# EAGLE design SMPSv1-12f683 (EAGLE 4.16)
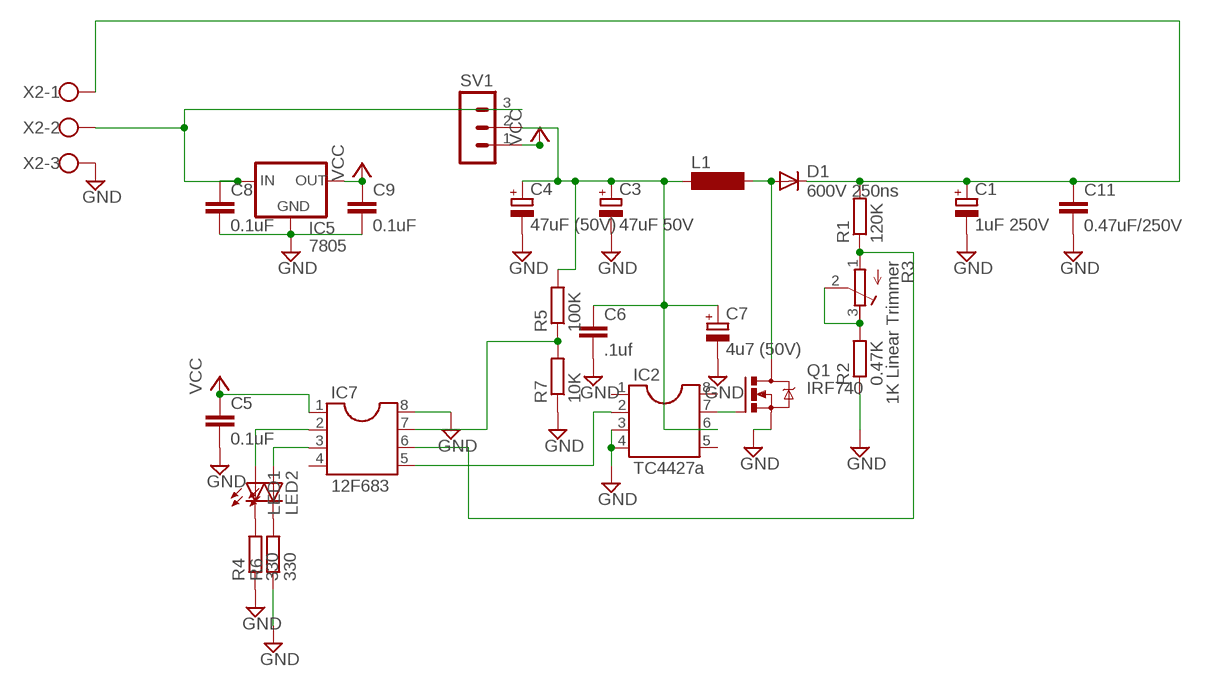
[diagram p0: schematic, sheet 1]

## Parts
C1  1uF 250V  CPOL-EUE2.5-6  [E2,5-6]
C3  47uF 50V  CPOL-EUE2.5-7  [E2,5-7]
C4  47uF (50V)  CPOL-EUE2.5-7  [E2,5-7]
C5  0.1uF  C2.5/2  [C2.5-2]
C6  .1uf  C2.5/2  [C2.5-2]
C7  4u7 (50V)  CPOL-EUE2.5-5  [E2,5-5]
C8  0.1uF  C2.5/2  [C2.5-2]
C9  0.1uF  C2.5/2  [C2.5-2]
C11  0.47uF/250V  C22/6  [C20.5B4]
D1  600V 250ns  BY448  [SOD57-10]
IC2  TC4427a  DIL8S  [SOCKED-08]
IC5  7805  78XXS  [78XXS]
IC7  12F683  DIL8S  [SOCKED-08]
L1  BS11  [BS11]
LED1  LED5MM  [LED5MM]
LED2  LED5MM  [LED5MM]
Q1  IRF740  [TO220BV]
R1  120K  R-EU_0204/7  [0204/7]
R2  0.47K  R-EU_0204/7  [0204/7]
R3  1K Linear Trimmer  R-TRIMM3339P  [RTRIM3339P]
R4  330  R-EU_0204/7  [0204/7]
R5  100K  R-EU_0204/7  [0204/7]
R6  330  R-EU_0204/7  [0204/7]
R7  10K  R-EU_0204/2V  [0204V]
SV1  MA03-1  [MA03-1]
X2  W237-3E  [W237-3E]

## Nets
GND: C1.- C3.- C4.- C5.2 C6.2 C7.- C8.2 C9.2 C11.2 IC2.3 IC2.4 IC5.GND IC7.8 Q1.S R2.1 R4.1 R6.1 R7.1 X2.3
N$1: D1.A L1.2 Q1.D
N$2: C3.+ C4.+ C6.1 C7.+ IC2.6 L1.1 R5.2 SV1.2
N$4: IC7.6 R1.1 R3.1(E)
N$5: R2.2 R3.2(S) R3.3(A)
N$6: IC2.7 Q1.G
N$7: IC2.2 IC7.5
N$8: LED1.K(C) R4.2
N$9: LED2.K(C) R6.2
N$10: C1.+ C11.1 D1.C R1.2 X2.1
N$13: IC7.3 LED2.A
N$14: IC7.2 LED1.A
N$17: C8.1 IC5.IN SV1.3 X2.2
N$30: IC7.7 R5.1 R7.2
VCC: C5.1 C9.1 IC5.OUT IC7.1 SV1.1
Unconnected: IC2.1 IC2.5 IC2.8 IC7.4

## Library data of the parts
C1 C3 C4 C7 = rcl:CPOL-EU: POLARIZED CAPACITOR, European symbol
C5 C6 C8 C9 = capacitor-wima:C: CAPACITOR
C11 = capacitor-HV:C: CAPACITOR
D1 = diode:BY448: DIODE
IC2 IC7 = ic-package:DIL8: Dual In Line
IC5 = v-reg:78XXS: VOLTAGE REGULATOR
L1 = inductor-neosid:BS: INDUCTOR
LED1 LED2 = led:LED: LED
Q1 = transistor-power:IRF740: N-CHANNEL MOS FET
R1 R2 R4-R7 = rcl:R-EU_: RESISTOR, European symbol
R3 = rcl:R-TRIMM: Trimm resistor
SV1 = con-lstb:MA03-1: PIN HEADER
X2 = con-wago-508:W237-3E: WAGO SREW CLAMP

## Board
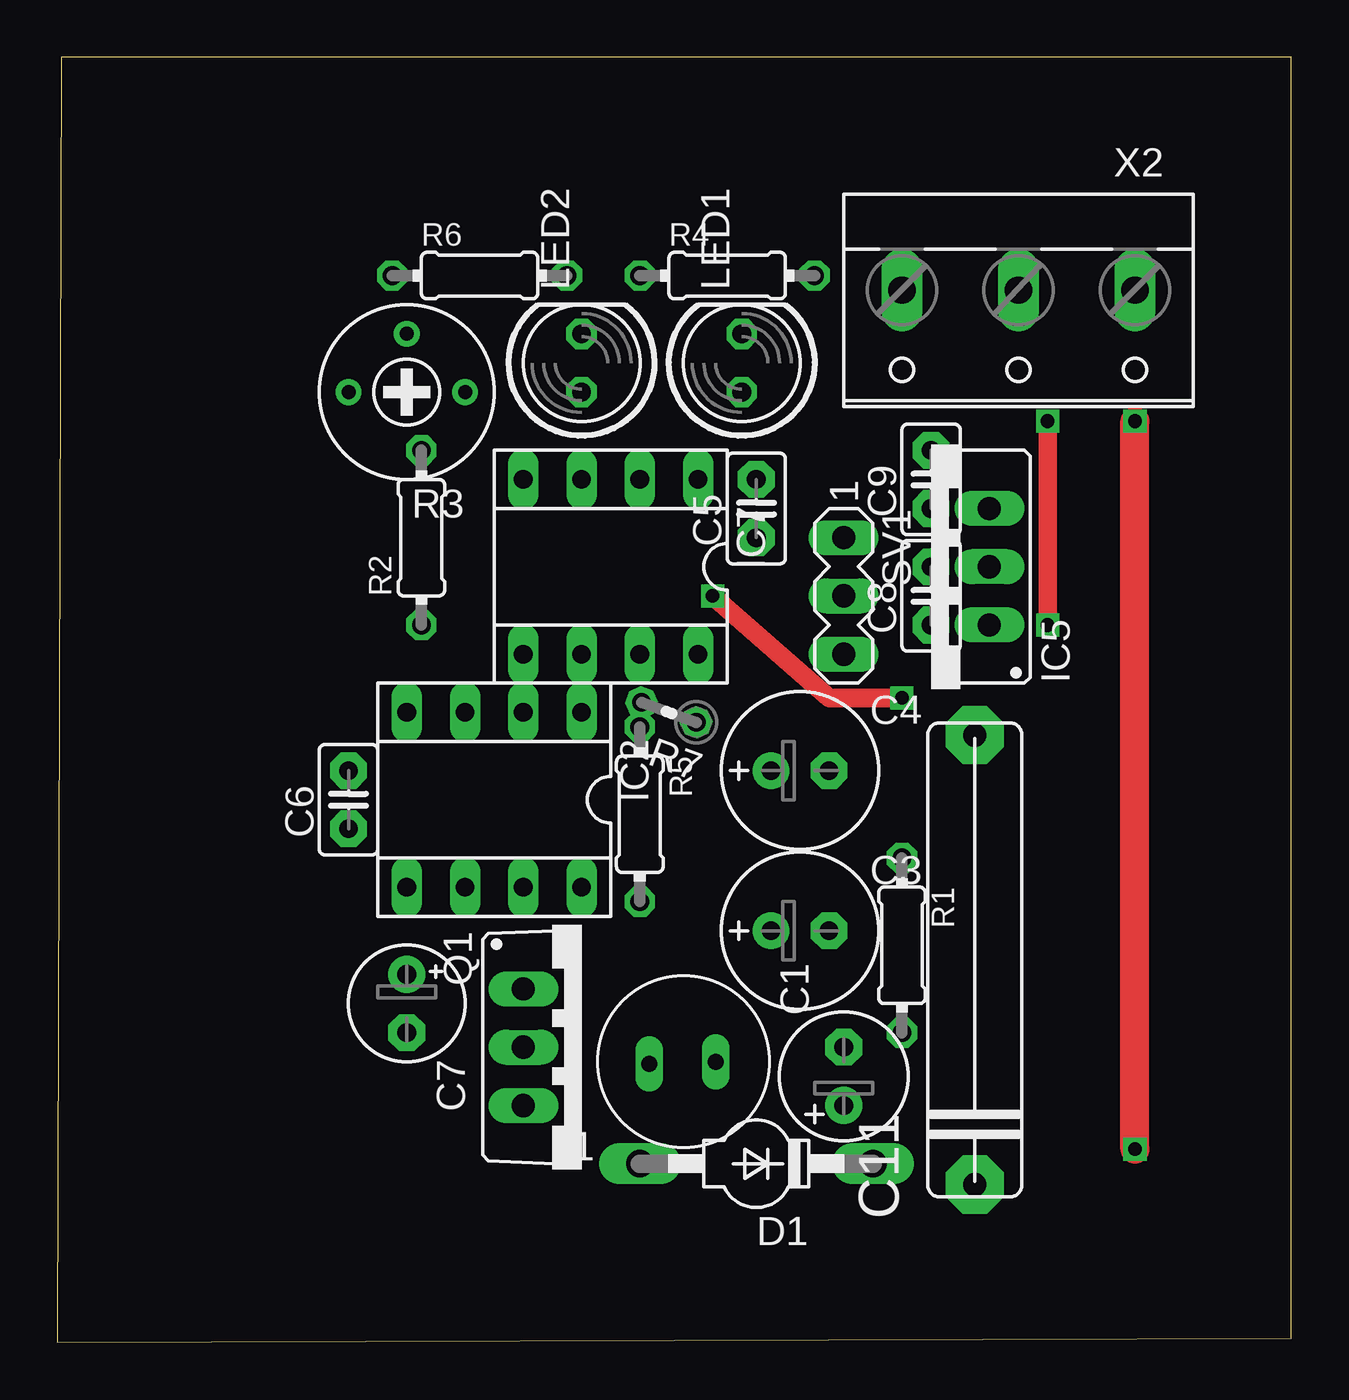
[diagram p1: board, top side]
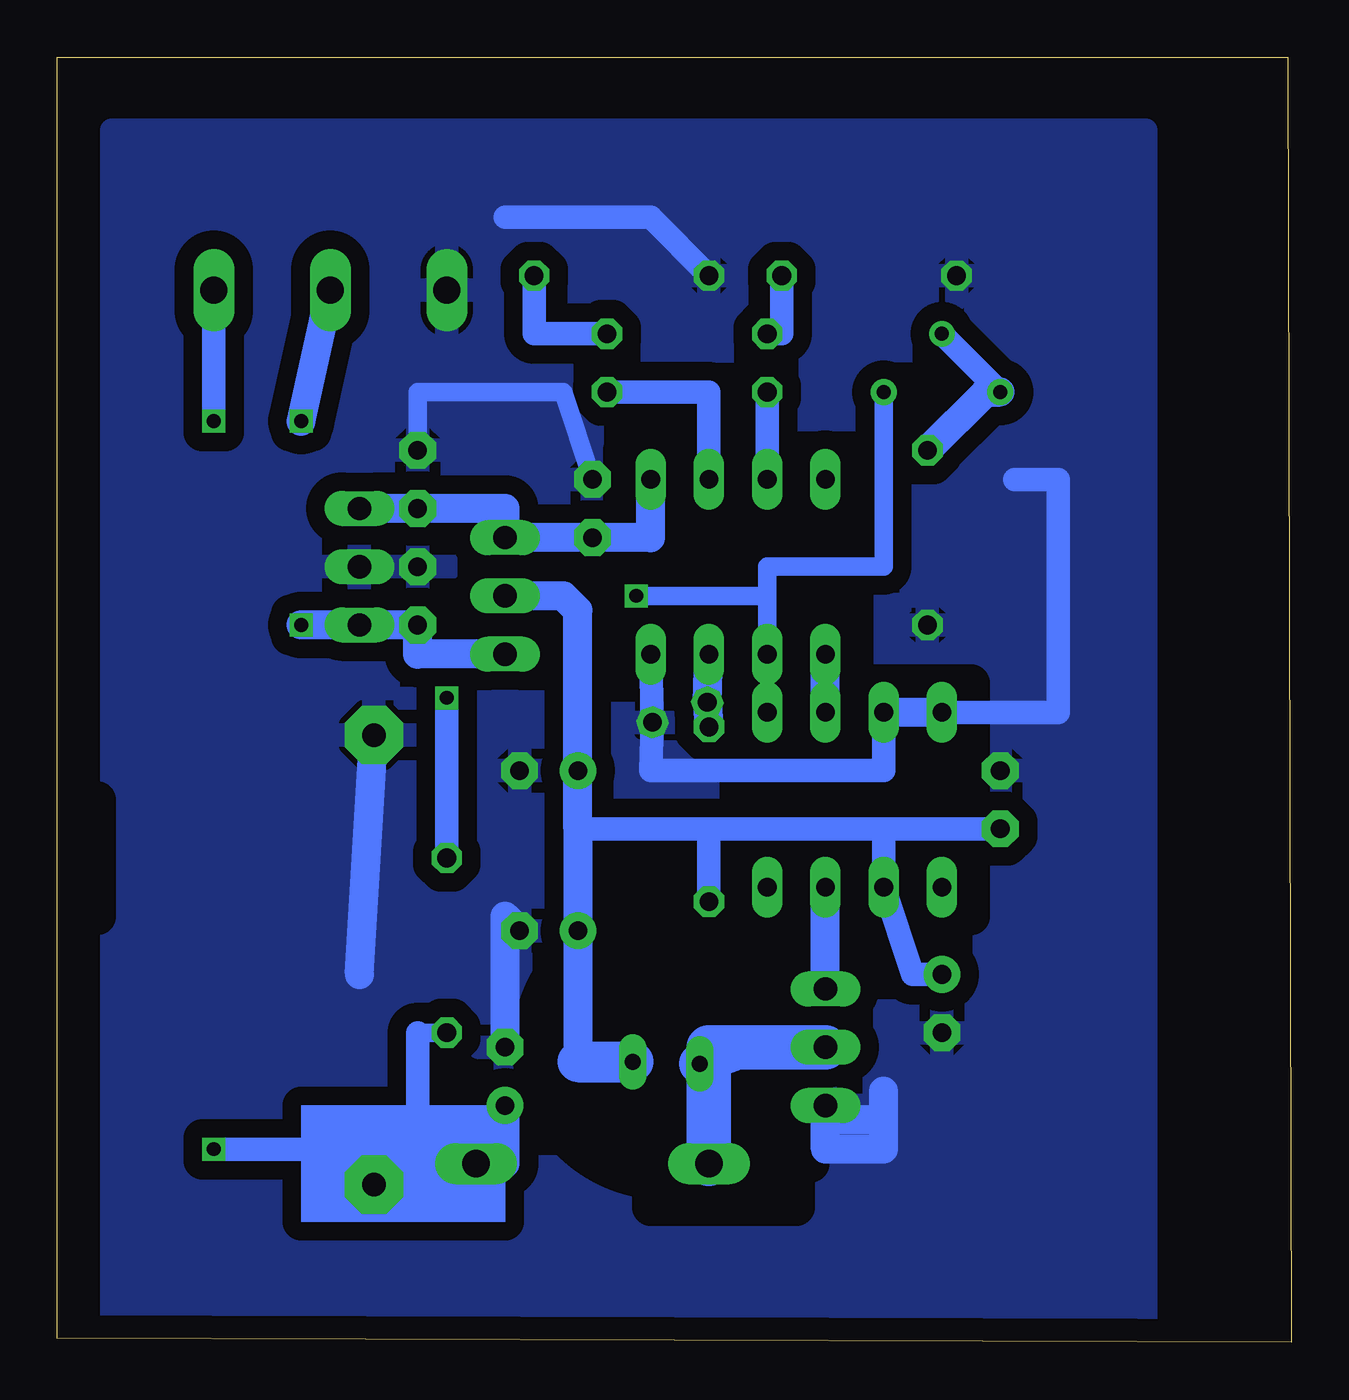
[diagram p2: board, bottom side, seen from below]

Size 53.81 x 56.04 mm. Coordinates in mm from the lower left corner, seen from the top.
Outline: 0,0 53.81,0.17 53.81,56.04 0.16,56.04 0,0
Copper layers (1*16): Top 0.035mm / dielectric 1.5mm / Bottom 0.035mm
Design rules "default": minimum track width 10mil, minimum drill 24mil, track to track 8mil, track to pad 8mil, pad to pad 8mil, via to via 8mil, smd to smd 8mil, copper to edge 40mil, drill to drill 8mil, minimum pad ring 10mil, minimum via ring 8mil, stop-mask expansion 4mil, vias tented up to drill 0mil, thermal gap 10mil
bRestrict: area 14,18.6 to 24.1,28.7; area 22.7,8.3 to 31.9,17.4; area 19,28.7 to 29.2,38.9; area 71.1,5.9 to 72.4,11; area 20.9,7.8 to 22.2,10.3; area 54.6,32.5 to 74.9,37.6; area 52.1,18.6 to 69.8,23.7; area 21.6,5.9 to 27.9,8.4

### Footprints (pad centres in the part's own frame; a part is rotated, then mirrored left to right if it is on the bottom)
E2,5-6 = drill 0.813 pad 1.6 round: + -1.27,0 | drill 0.813 pad 1.6 octagon: - 1.27,0
E2,5-7 = drill 0.813 pad 1.6 round: + -1.27,0 | drill 0.813 pad 1.6 octagon: - 1.27,0
C2.5-2 = drill 0.813 pad 1.6 octagon: 1 -1.27,0; 2 1.27,0
E2,5-5 = drill 0.813 pad 1.6 round: + -1.27,0 | drill 0.813 pad 1.6 octagon: - 1.27,0
C20.5B4 = drill 1.016 pad 2.54 octagon: 1 -9.803,0; 2 9.803,0
SOD57-10 = drill 1.194 long: A 5.08,0; C -5.08,0
SOCKED-08 = drill 0.813 long: 1 -3.81,-3.81; 2 -1.27,-3.81; 3 1.27,-3.81; 4 3.81,-3.81; 5 3.81,3.81; 6 1.27,3.81; 7 -1.27,3.81; 8 -3.81,3.81
78XXS = drill 1.016 long: GND 0,-2.54; IN -2.54,-2.54; OUT 2.54,-2.54
BS11 = drill 0.7 long: 1 -1.415,0; 2 1.502,0.087
LED5MM = drill 0.813 octagon: A -1.27,0; K 1.27,0
TO220BV = drill 1.016 long: D 0,-2.54; G -2.54,-2.54; S 2.54,-2.54
0204/7 = drill 0.813 octagon: 1 -3.81,0; 2 3.81,0
RTRIM3339P = drill 0.61 round: 1 -2.54,0; 2 0,-2.54; 3 2.54,0
0204V = drill 0.813 octagon: 1 -1.27,0; 2 1.27,0
MA03-1 = drill 1.016 long: 1 -2.54,0; 2 0,0; 3 2.54,0
W237-3E = drill 1.194 long: 1 -5.08,-0.635; 2 0,-0.635; 3 5.08,-0.635

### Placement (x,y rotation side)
C1  34.28,11.6 90 top
C3  32.38,17.95 0 top
C4  32.38,24.93 0 top
C5  30.48,36.36 90 top
C6  12.7,23.66 90 top
C7  15.23,14.77 270 top
C8  38.09,32.55 90 top
C9  38.09,37.63 90 top
C11  40,16.68 90 top
D1  30.48,7.79 180 top
IC2  19.05,23.66 180 top
IC5  38.09,33.82 90 top
IC7  24.12,33.82 180 top
L1  27.3,12.23 180 top
LED1  29.84,42.71 90 top
LED2  22.86,42.71 90 top
Q1  22.86,12.87 270 top
R1  36.83,17.31 270 top
R2  15.87,35.09 90 top
R3  15.23,41.44 180 top
R4  29.21,46.52 0 top
R5  25.39,23.03 270 top
R6  18.41,46.52 0 top
R7  26.66,27.47 160 top
SV1  34.28,32.55 270 top
X2  41.91,45.25 180 top

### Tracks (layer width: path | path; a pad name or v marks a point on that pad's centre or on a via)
GND
  Bottom 0.813: C5.2 31.75,41.44 38.09,41.44 C9.2
  Bottom 1.016: 34.28,49.06 27.93,49.06 R4.1 | 12.06,37.63 10.16,37.63 10.16,27.47 IC2.4 IC2.3 17.77,24.93 27.93,24.93 R7.1 IC7.8
  Bottom 1.27: IC2.4 IC2.3 | 20.32,9.69 Q1.S | 20.32,9.69 20.32,8.42 17.77,8.42 17.77,9.69 | 17.77,9.69 20.32,9.69 | 17.77,9.69 17.77,10.96 | C1.- 34.28,18.58 C3.- | 40.64,16.04 C11.2
  pour Bottom (isolate 0.813): 6.35,52.87 51.43,52.87 51.43,0.8 6.35,0.8
N$1
  Bottom 1.778: L1.2 24.12,12.78 25.39,12.87
  Bottom 1.93: Q1.D 25.39,12.87 D1.A
N$2
  Bottom 1.016: C7.+ 16.51,16.04 IC2.6 17.77,22.39 | 17.77,22.39 C6.1 | 17.77,22.39 25.39,22.39 | 25.39,22.39 31.11,22.39 | 25.39,22.39 R5.2
  Bottom 1.27: 31.11,12.23 C3.+ 31.11,22.39 C4.+ 31.11,31.91 31.75,32.55 SV1.2
  Bottom 1.778: 31.11,12.23 L1.1
N$4  (via drill 0.6)
  Top 0.813: v36.83,28.11 33.65,28.11 v28.57,32.55
  Bottom 0.813: v28.57,32.55 22.86,32.55 IC7.6 22.86,33.82 17.77,33.82 R3.1
  Bottom 1.016: v36.83,28.11 R1.1
N$5
  Bottom 1.016: R3.3 R3.2
  Bottom 1.27: R3.3 13.33,41.44 R2.2
N$6
  Bottom 1.27: Q1.G IC2.7
N$7
  Bottom 1.27: IC2.2 IC7.5
N$8
  Bottom 1.016: LED1.K 33.02,43.98 R4.2
N$9
  Bottom 1.016: LED2.K 22.22,43.98 R6.2
N$10  (via drill 0.6)
  Top 1.27: v46.98,8.42 v46.98,40.17
  Bottom 0.813: 38.09,13.5 R1.2 | 38.09,8.42 38.4,8.11 38.41,8.11
  Bottom 1.016: 36.83,7.15 36.83,7.35 36.86,7.35 | 38.09,13.5 38.09,8.42 v46.98,8.42 | v46.98,40.17 X2.1
  Bottom 1.27: 38.09,7.79 38.41,8.11 39.34,9.08 41.25,6.6 | 38.09,7.79 38.09,5.88 | 38.09,7.79 C11.1 | C1.+ 34.28,7.79 D1.C
  Bottom 1.93: D1.C 36.86,7.35 41.25,6.6
N$13
  Bottom 1.016: IC7.3 LED2.A
N$14
  Bottom 1.016: LED1.A 25.39,41.44 IC7.2
N$17  (via drill 0.6)
  Top 0.813: v43.17,31.28 v43.17,40.17
  Bottom 1.27: v43.17,31.28 IC5.IN C8.1 38.09,30.01 SV1.3 | v43.17,40.17 X2.2
N$30
  Bottom 0.813: R7.2 25.39,27.9
  Bottom 1.27: R5.1 R7.2 IC7.7
VCC
  Bottom 1.016: C5.1 30.48,35.12
  Bottom 1.27: IC5.OUT C9.1 34.28,36.36 SV1.1 C5.1 27.93,35.09 IC7.1
(copper drawn outside any net)
  shapes: Bottom area x3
